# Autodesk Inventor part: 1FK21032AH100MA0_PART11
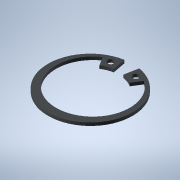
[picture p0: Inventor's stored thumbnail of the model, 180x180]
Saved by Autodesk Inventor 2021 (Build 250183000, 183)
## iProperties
Created: 2025-04
Part Number: 1FK21032AH100MA0_PART11
Material: Generic
Catalog Web Link: www.3dfindit.com
Description: -Servo synchronous motor
Document SubType Name: Modeling
Designer: psAdmin
Mass: 0.288797 g
Surface Area: 7.43416 cm^2
Volume: 0.288797 cm^3
Density: 1 g/cm^3
Appearance: PSOLRGB-212-217-219
Category: PARTsolutions
Title: 1FK21032AH100MA0_PART11
Author: Cadenas PARTsolutions
Comments: Servo synchronous motor
Sending System: PARTsolutions
Preprocessor: ST-DEVELOPER v19.3
PSOL_IDENT_0: {$CADENAS_DATA/23d-libs/siemens_ag/_cat_/12/33/1fk21032ah100ma0.prj},216 {VTYP=3D},{NB=1FK21032AH100
PSOL_IDENT_1: MA0_PART11},{LINA=1FK21032AH100MA0_PART11},{NN=1FK21032AH100MA0_PART11},{NOPRJ=TRUE},{DATE=19.08.202
PSOL_IDENT_2: 5 14:00:27},{GEOMDATE=30.07.2025 02:02:58},{VERSION=},{LINEID=10},{WBVAR=},{WBNUMERIC=}  {NB=1FK2103
PSOL_IDENT_3: 2AH100MA0_PART11},{LINA=1FK21032AH100MA0_PART11},{KT=DUMMY},{PREVIEW=../../../_pool_/d3/78/p_d211_xx
PSOL_IDENT_4: _00934j.png},{DESCSHORT=SIMOTICS S-1FK2 HD, SINAMICS S210 3AC 400V-480V, 0.59 Nm, 4500 rpm},{DESCLON
PSOL_IDENT_5: G=SIMOTICS S-1FK2 HD servo motor M0=0.64 Nm; PN = 0.28 kW at nN=4500 rpm (380-480 V); PN = 0.167 kW
PSOL_IDENT_6: at nN=2500 rpm (200-240 V); with holding brake; degree of protection IP64; cylindrical shaft D14 x 3
PSOL_IDENT_7: 0 mm; absolute encoder 22-bit + 12-bit multiturn (encoder AM22DQC); with OCC interface; plug size M1
PSOL_IDENT_8: 7, rotatable; SIMOTICS S-1FK2 servomotorfor a wide range of uses in industrial environments. SIMOTIC
PSOL_IDENT_9: S S‑1FK2 servomotors are compact synchronous motors with a high dynamic performance that set themsel
PSOL_IDENT_10: ves apart as a result of their high power density, degree of protection and overload capability. The
PSOL_IDENT_11: motors are available in two variants: as High Dynamic variant (highest dynamic performance as a res
PSOL_IDENT_12: ult of the low intrinsic moment of inertia for applications demanding a high dynamic performance wit
PSOL_IDENT_13: h low moved masses) - and as Compact variant (precise and stable closed-loop control for medium up t
PSOL_IDENT_14: o large moved masses as a result of a medium intrinsic moment of inertia). SIMOTICSS‑1FK2 servomotor
PSOL_IDENT_15: s fully exploit their strengths in a system with the SINAMICSS210 frequency converter and simple con
PSOL_IDENT_16: nection using the one cable connection (OCC). Advantages include the short control and positioning t
PSOL_IDENT_17: imes, fast and precise correction of disturbing quantities as well as stable control with a high dyn
PSOL_IDENT_18: amic performance. The servo motors can be configured to address a wide range of requirements. For ex
PSOL_IDENT_19: ample with and without holding brake, IP64 or IP65 degree of protection, singleturn or multiturn abs
PSOL_IDENT_20: olute encoders - to name just a few. Further, the servomotors are available in different shaft heigh
PSOL_IDENT_21: ts extending from 20 to 100. A shaft sealing ring is available to achieve an IP65 degree of protecti
PSOL_IDENT_22: on and for subsequent mounting at the motor or as spare part. SIMOTICS - the optimum motor for each
PSOL_IDENT_23: and every motion control application.},{INTNO=195125315563},{SUPPLIERALTNO=1FK2103-2AH10-0MA0},{MANU
PSOL_IDENT_24: ID=1FK21032AH100MA0},{MANUNAME=Siemens},{MANUTYPEDESC=SYNCHRONOUS MOTOR 1FK2 HD 0,64 NM},{AAU732=SIM
PSOL_IDENT_25: OTICS},{AAO057=S-1FK2},{AAU734=SIMOTICS S-1FK2 HD servo motor M0=0.64 Nm; PN = 0.28 kW at nN=4500 rp
PSOL_IDENT_26: m (380-480 V); PN = 0.167 kW at nN=2500 rpm (200-240 V); with holding brake; degree of protection IP
PSOL_IDENT_27: 64; cylindrical shaft D14 x 30 mm; absolute encoder 22-bit + 12-bit multiturn (encoder AM22DQC); wit
PSOL_IDENT_28: h OCC interface; plug size M17, rotatable;},{AAW338=SYNCHRONOUS MOTOR 1FK2 HD 0,64 NM},{AAO742=SIMOT
PSOL_IDENT_29: ICS},{AAO663=4034106444723},{NOCUPEROU=1},{PRICEQUANTITY=1},{QUANTITYMIN=1},{QUANTITYINT=1},{CTN=850
PSOL_IDENT_30: 15100},{COO=RO},{AAO676=1FK2103-2AH10-0MA0},{AAO677=Siemens AG},{ORDERUNIT=C62},{CONTENTUNIT=C62}
NB: 1FK21032AH100MA0_PART11
NT: Servo synchronous motor
NBSYN: $MANUID._PART11
LINA: 1FK21032AH100MA0_PART11
CATALOG: SIEMENS
PREVIEW: ../../../_pool_/d3/78/p_d211_xx_00934j.png
DESCSHORT: SIMOTICS S-1FK2 HD, SINAMICS S210 3AC 400V-480V, 0.59 Nm, 4500 rpm
DESCLONG: SIMOTICS S-1FK2 HD servo motor M0=0.64 Nm; PN = 0.28 kW at nN=4500 rpm (380-480 V); PN = 0.167 kW at nN=2500 rpm (200-240 V); with holding brake; degree of prot
INTNO: 195125315563
SUPPLIERALTNO: 1FK2103-2AH10-0MA0
MANUID: 1FK21032AH100MA0
MANUNAME: Siemens
MANUTYPEDESC: SYNCHRONOUS MOTOR 1FK2 HD 0,64 NM
AAU732: SIMOTICS
AAO057: S-1FK2
AAU734: SIMOTICS S-1FK2 HD servo motor M0=0.64 Nm; PN = 0.28 kW at nN=4500 rpm (380-480 V); PN = 0.167 kW at nN=2500 rpm (200-240 V); with holding brake; degree of prot
AAW338: SYNCHRONOUS MOTOR 1FK2 HD 0,64 NM
AAO742: SIMOTICS
AAO663: 4034106444723.0
NOCUPEROU: 1
PRICEQUANTITY: 1
QUANTITYMIN: 1
QUANTITYINT: 1
CTN: 85015100
COO: RO
ARTICLENO: 1FK21032AH100MA0_PART11
BOMINFO: 1FK21032AH100MA0_PART11
CREATOR: CADENAS GmbH
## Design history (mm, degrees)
feature "2025_04_17_15_06_16_0705"
body "Solid1"
